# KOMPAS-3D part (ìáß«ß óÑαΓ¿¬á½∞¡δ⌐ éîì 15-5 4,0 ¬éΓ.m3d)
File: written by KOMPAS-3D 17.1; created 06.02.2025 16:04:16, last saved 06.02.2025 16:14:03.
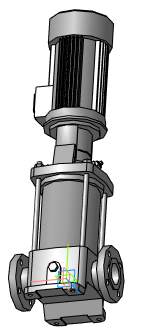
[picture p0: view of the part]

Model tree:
1. Операция без истории:1  (labels: Насос вертикальный ВМН 15-5 4,0 кВт)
